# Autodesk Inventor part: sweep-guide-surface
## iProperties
Created: 2006-01
Part Number: sweep-guide-surface
Document SubType Name: Modeling
Designer: CADCIM
Density: 1 g/cm^3
Author: CADCIM
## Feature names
1. Extrusion1
